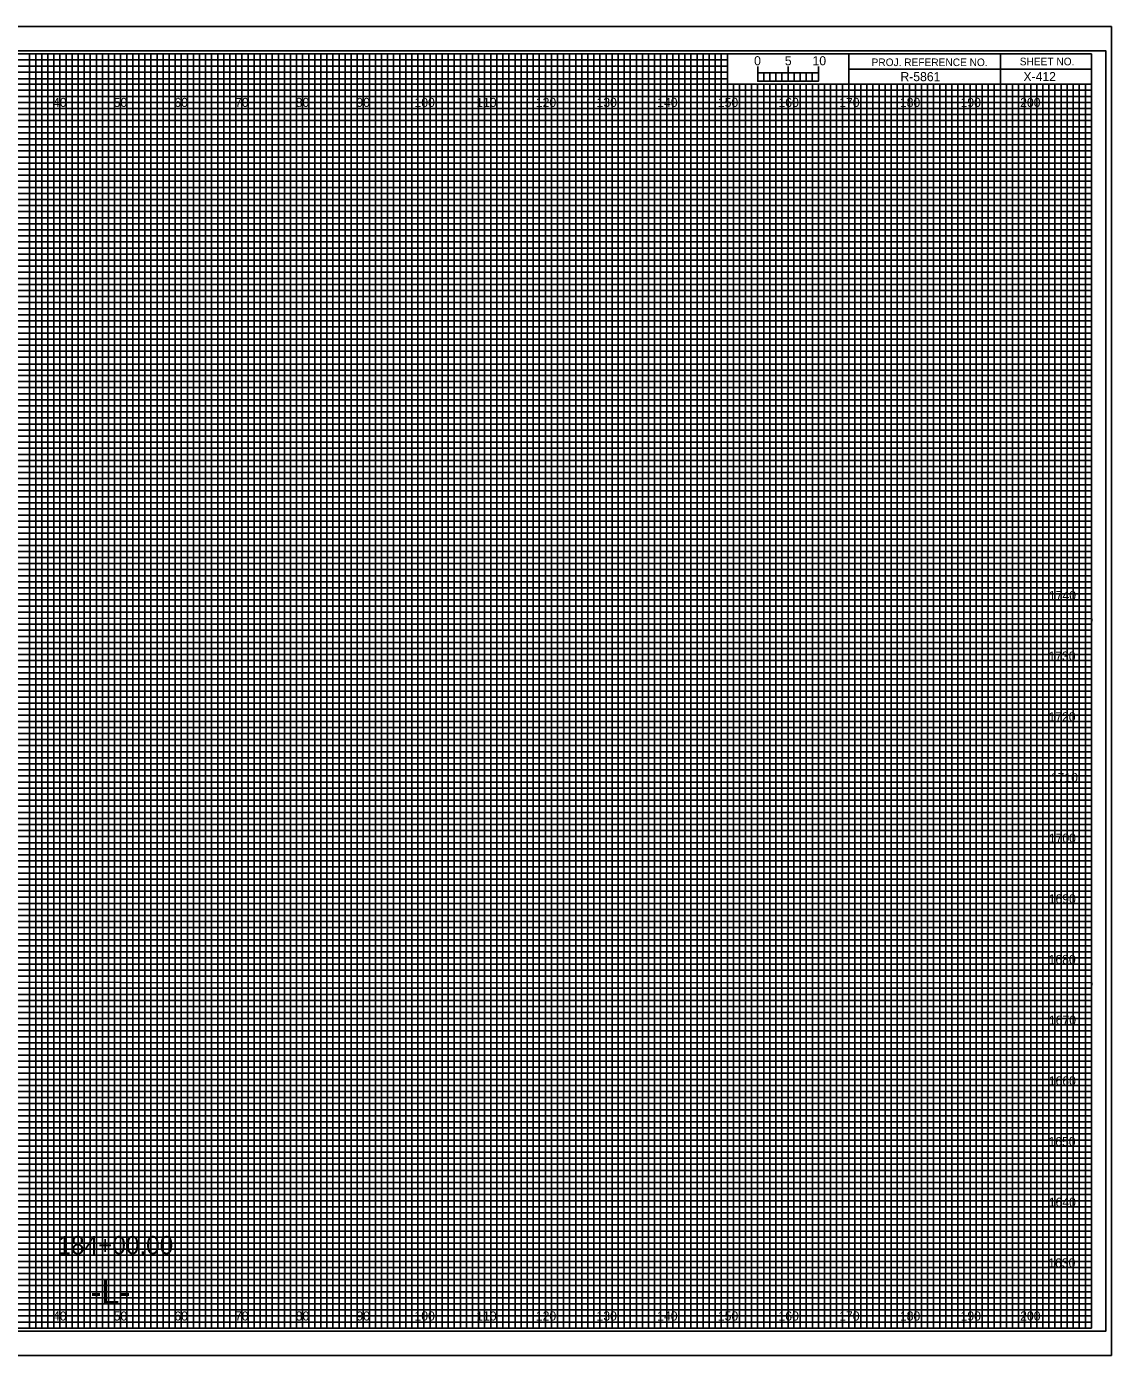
# Model space of a CAD drawing. Extents: x -13 to 323, y -5 to 6154.
# Drawn here: x 144.5 to 323.3, y 1755.5 to 1974.5 of the extents above; entities that cross this region are included whole.
import ezdxf

# ---------------------------------------------------------------- set-up
doc = ezdxf.new("R2010")
doc.units = 0
for name, color, linetype in [('Exist CMT Ground Line', 7, 'Continuous'), ('Prop Horizontal Alignment', 7, 'Continuous'), ('Prop Retaining Wall', 7, 'Continuous'), ('Prop XS Alignment Label', 7, 'Continuous'), ('Prop XS Bar Scale Labels', 7, 'Continuous'), ('Prop XS DDE', 7, 'Continuous'), ('Prop XS DDE Elevations', 7, 'Continuous'), ('Prop XS DDE Slope Text', 7, 'Continuous'), ('Prop XS Earthwork Shape', 7, 'Continuous'), ('Prop XS Elevation Labels', 7, 'Continuous'), ('Prop XS Project Number', 7, 'Continuous'), ('Prop XS Sheet Number', 7, 'Continuous'), ('Prop XS Station Labels', 7, 'Continuous'), ('Raster_Level_0', 7, 'Continuous'), ('Scratch_Level_3', 7, 'Continuous'), ('Sheet Cutting Line CELL', 7, 'Continuous')]:
    doc.layers.add(name, color=color, linetype=linetype)

msp = doc.modelspace()

# ---------------------------------------------------------------- linework, layer by layer
at = {"layer": 'Exist CMT Ground Line'}
for p, q in [((265, 1965.49), (265, 1967.9)), ((265, 1966.9), (265, 1967.9)), ((270, 1965.49), (270, 1967.9)), ((275, 1965.49), (275, 1967.9)), ((275, 1966.9), (275, 1967.9))]:
    msp.add_line(p, q, dxfattribs=at)
for points in [[(275, 1966.9), (265, 1966.9), (265, 1965.49), (275, 1965.49)], [(265, 1966.9), (266, 1966.9), (266, 1965.49), (265, 1965.49)], [(267, 1966.9), (268, 1966.9), (268, 1965.49), (267, 1965.49)], [(269, 1966.9), (270, 1966.9), (270, 1965.49), (269, 1965.49)], [(271, 1966.9), (272, 1966.9), (272, 1965.49), (271, 1965.49)], [(273, 1966.9), (274, 1966.9), (274, 1965.49), (273, 1965.49)]]:
    msp.add_lwpolyline(points, close=True, dxfattribs=at)
at = {"layer": 'Prop Retaining Wall'}
for p, q in [((0, 1969), (260, 1969)), ((260, 1969), (260, 1967.98)), ((260, 1967.98), (0, 1967.98)), ((0, 1967), (260, 1967)), ((260, 1967), (260, 1965.89)), ((260, 1965.89), (0, 1965.89)), ((0, 1964), (320, 1964))]:
    msp.add_line(p, q, dxfattribs=at)
for points in [[(0, 1963), (270, 1963), (320, 1963), (320, 1962), (0, 1962)], [(0, 1961), (320, 1961), (320, 1959), (0, 1959)], [(0, 1958), (320, 1958), (320, 1957), (0, 1956.98)], [(0, 1956), (320, 1956), (320, 1954), (0, 1954)], [(0, 1953), (320, 1953), (320, 1952), (0, 1952)], [(0, 1951), (320, 1951), (320, 1949), (0, 1949)], [(0, 1948), (320, 1948), (320, 1947), (0, 1947)], [(0, 1946), (320, 1946), (320, 1944), (0, 1944)], [(0, 1943), (320, 1943), (320, 1942), (0, 1942)], [(0, 1941), (320, 1941), (320, 1939), (0, 1939)], [(0, 1938), (320, 1938), (320, 1937), (0, 1937)], [(0, 1936), (320, 1936), (320, 1933.95), (320, 1933), (320, 1932), (0, 1932)], [(0, 1934), (320, 1934), (320, 1933), (0, 1933)], [(0, 1931), (320, 1931), (320, 1929), (0, 1929.03)], [(0, 1929.03), (320, 1929), (320, 1928), (0, 1928)], [(0, 1927), (320, 1927), (320, 1926), (0, 1926)], [(0, 1924), (320, 1924), (320, 1923), (0, 1923)], [(0, 1922), (320, 1922), (320, 1921), (0, 1921)], [(-0.07, 1918.89), (320, 1918.89), (320, 1917.88), (-0.07, 1917.88)], [(0, 1917), (320, 1917), (320, 1916), (0, 1916)], [(0, 1914), (320, 1914), (320, 1913), (0, 1913)], [(0, 1912), (320, 1912), (320, 1911), (0, 1911)], [(0, 1909), (320, 1909), (320, 1908), (0, 1908)], [(0, 1907), (320, 1907), (320, 1906), (0, 1906)], [(0, 1904), (320, 1904), (320, 1903), (0, 1903)], [(0, 1902), (320, 1902), (320, 1901), (0, 1901)], [(0, 1899), (320, 1899), (319.99, 1897.98), (0, 1898)], [(0, 1897), (320, 1897), (320, 1896), (0, 1896)], [(0, 1894), (320, 1894), (320, 1893), (0, 1893)], [(0, 1892), (320, 1892), (320, 1891), (0, 1891)], [(0, 1889), (320, 1889), (320, 1888), (0, 1888)], [(0, 1887), (320, 1887), (320, 1886), (0, 1886)], [(0, 1884), (320, 1884), (320, 1883), (0, 1883)], [(0, 1882), (320, 1882), (320, 1881), (0, 1881)], [(0, 1879), (320, 1879), (320, 1878), (0, 1878)], [(0, 1876.99), (320.07, 1876.91), (320, 1876), (0, 1876)], [(0, 1874), (320, 1874), (320, 1873), (0, 1873)], [(0, 1872), (320, 1872), (320, 1871), (0, 1871)], [(0, 1869), (320, 1869), (320, 1868), (0, 1868)], [(0, 1867), (320, 1867), (320, 1866), (0, 1866)], [(0, 1864), (320, 1864), (320, 1863), (0, 1863)], [(0, 1862), (320, 1862), (320, 1861), (0, 1861)], [(0, 1859), (320, 1859), (320, 1858), (0, 1858)], [(0, 1857), (320, 1857), (320, 1856), (0, 1856)], [(0, 1854), (320, 1854), (320, 1853), (0, 1853)], [(0, 1852), (320, 1852), (320, 1851), (0, 1851)], [(0, 1849), (320, 1849), (320, 1848), (0, 1848)], [(0, 1847), (320, 1847), (320, 1846), (0, 1846)], [(0, 1844), (320, 1844), (320, 1843), (0, 1843)], [(0, 1842), (320, 1842), (320, 1841), (0, 1841)], [(0, 1839), (320, 1839), (319.99, 1837.98), (0, 1838)], [(0, 1837), (320, 1837), (320, 1836), (0, 1836)], [(0, 1834), (320, 1834), (320, 1833), (0, 1833)], [(0, 1832), (320, 1832), (320, 1831), (0, 1831)], [(0, 1829), (320, 1829), (320, 1828), (0, 1828)], [(0, 1827), (320, 1827), (320, 1826), (0, 1826)], [(0, 1824), (320, 1824), (320, 1823), (0, 1823)], [(0, 1822), (320, 1822), (320, 1821), (0, 1821)], [(0, 1819), (320, 1819), (320, 1818), (0, 1818)], [(0, 1816.99), (320.07, 1816.91), (320, 1816), (0, 1816)], [(0, 1814), (320, 1814), (320, 1813), (0, 1813)], [(0, 1812), (320, 1812), (320, 1811), (0, 1811)], [(0, 1809), (320, 1809), (320, 1808), (0, 1808)], [(0, 1807), (320, 1807), (320, 1806), (0, 1806)], [(0, 1804), (320, 1804), (320, 1803), (0, 1803)], [(0, 1802), (320, 1802), (320, 1801), (0, 1801)], [(0, 1799), (320, 1799), (320, 1798), (0, 1798)], [(0, 1797), (320, 1797), (320, 1796), (0, 1796)], [(0, 1794), (320, 1794), (320, 1793), (0, 1793)], [(0, 1792), (320, 1792), (320, 1791), (0, 1791)], [(0, 1789), (320, 1789), (320, 1788), (0, 1788)], [(0, 1787), (320, 1787), (320, 1786), (0, 1786)], [(0, 1784), (320, 1784), (320, 1783), (0, 1783)], [(0, 1782), (320, 1782), (320, 1781), (0, 1781)], [(0, 1779), (320, 1779), (320, 1778), (0, 1778)], [(0, 1777), (320, 1777), (320, 1776), (0, 1776)], [(0, 1774), (320, 1774), (320, 1773), (0, 1773)], [(0, 1772), (320, 1772), (320, 1771), (0, 1771)], [(0, 1769), (320, 1769), (320, 1768), (0, 1768)], [(0, 1767), (320, 1767), (320, 1766), (0, 1766)], [(0, 1764), (320, 1764), (320, 1763), (0, 1763)], [(0, 1762), (320, 1762), (320, 1761), (0, 1761)]]:
    msp.add_lwpolyline(points, dxfattribs=at)
at = {"layer": 'Prop XS Alignment Label'}
for p, q in [((305, 1970), (305, 1965)), ((305, 1965), (305, 1970)), ((280, 1967.5), (280, 1965)), ((320, 1967.49), (280, 1967.49)), ((280, 1965), (320, 1965))]:
    msp.add_line(p, q, dxfattribs=at)
for points in [[(320, 1970), (0, 1970), (0, 1760), (320, 1760)], [(280, 1970), (260, 1970), (260, 1965.03), (280, 1965.03)], [(320, 1970), (280, 1970), (280, 1965), (320, 1965)]]:
    msp.add_lwpolyline(points, close=True, dxfattribs=at)
at = {"layer": 'Prop XS DDE'}
msp.add_lwpolyline([(-13.4, 1755.5), (323.3, 1755.5), (323.3, 1974.5), (-13.4, 1974.5)], close=True, dxfattribs=at)
at = {"layer": 'Prop XS DDE Elevations'}
for p, q in [((150, 1760), (150, 1970)), ((160, 1760), (160, 1970)), ((170, 1760), (170, 1970)), ((180, 1760), (180, 1970)), ((190, 1760), (190, 1970)), ((200, 1760), (200, 1970)), ((210, 1760), (210, 1970)), ((220, 1760), (220, 1970)), ((230, 1760), (230, 1970)), ((240, 1760), (240, 1970)), ((250, 1760), (250, 1970)), ((260, 1760), (260, 1964.69)), ((270, 1760), (270, 1964.69)), ((280, 1760), (280, 1964.69)), ((290, 1760), (290, 1964.69)), ((300, 1760), (300, 1964.69)), ((310, 1760), (310, 1964.69)), ((0, 1960), (320, 1960)), ((0, 1950), (320, 1950)), ((0, 1940), (320, 1940)), ((0, 1930), (320, 1930)), ((0, 1920), (320, 1920)), ((0, 1910), (320, 1910)), ((0, 1900), (320, 1900)), ((0, 1890), (320, 1890)), ((0, 1880), (320, 1880)), ((0, 1870), (320, 1870)), ((0, 1860), (320, 1860)), ((0, 1850), (320, 1850)), ((0, 1840), (320, 1840)), ((0, 1830), (320, 1830)), ((0, 1820), (320, 1820)), ((0, 1810), (320, 1810)), ((0, 1800), (320, 1800)), ((0, 1790), (320, 1790)), ((0, 1780), (320, 1780)), ((0, 1770), (320, 1770))]:
    msp.add_line(p, q, dxfattribs=at)
at = {"layer": 'Prop XS DDE Slope Text'}
msp.add_lwpolyline([(-10.8, 1759.5), (322.4, 1759.5), (322.4, 1970.5), (-10.8, 1970.5)], close=True, dxfattribs=at)
at = {"layer": 'Prop XS Earthwork Shape'}
for p, q in [((150, 1970), (140, 1970)), ((150, 1760), (150, 1970)), ((170, 1970), (160, 1970)), ((160, 1970), (160, 1760)), ((170, 1760), (170, 1970)), ((190, 1970), (180, 1970)), ((180, 1970), (180, 1760)), ((190, 1760), (190, 1970)), ((210, 1970), (200, 1970)), ((200, 1970), (200, 1760)), ((210, 1760), (210, 1970)), ((230, 1970), (220, 1970)), ((220, 1970), (220, 1760)), ((230, 1760), (230, 1970)), ((250, 1970), (240, 1970)), ((240, 1970), (240, 1760)), ((250, 1760), (250, 1970)), ((260, 1970), (260, 1760)), ((270, 1760), (270, 1965)), ((290, 1965), (280, 1965)), ((280, 1965), (280, 1760)), ((290, 1760), (290, 1965)), ((310, 1965), (300, 1965)), ((300, 1965), (300, 1760)), ((310, 1760), (310, 1965)), ((160, 1760), (150, 1760)), ((180, 1760), (170, 1760)), ((200, 1760), (190, 1760)), ((220, 1760), (210, 1760)), ((240, 1760), (230, 1760)), ((260, 1760), (250, 1760)), ((280, 1760), (270, 1760)), ((300, 1760), (290, 1760)), ((320, 1760), (310, 1760)), ((320, 1760), (320, 1760))]:
    msp.add_line(p, q, dxfattribs=at)
for points in [[(0, 1960), (320, 1960), (320, 1950), (0, 1950)], [(0, 1940), (320, 1940), (320, 1930), (0, 1930)], [(0, 1920), (320, 1920), (320, 1910), (0, 1910)], [(0, 1900), (320, 1900), (320, 1890), (0, 1890)], [(0, 1880), (320, 1880), (320, 1870), (0, 1870)], [(0, 1860), (320, 1860), (320, 1850), (0, 1850)], [(0, 1840), (320, 1840), (320, 1830), (0, 1830)], [(0, 1820), (320, 1820), (320, 1810), (0, 1810)], [(0, 1800), (320, 1800), (320, 1790), (0, 1790)], [(0, 1780), (320, 1780), (320, 1770), (0, 1770)]]:
    msp.add_lwpolyline(points, dxfattribs=at)
at = {"layer": 'Prop XS Elevation Labels'}
for p, q in [((267, 1965), (266.01, 1965)), ((266.01, 1965), (266.01, 1760)), ((267, 1760), (267, 1965)), ((269, 1965), (268, 1965)), ((268, 1965), (268, 1760)), ((269, 1760), (269, 1965)), ((266.01, 1760), (265, 1760)), ((268, 1760), (267, 1760))]:
    msp.add_line(p, q, dxfattribs=at)
for points in [[(145, 1760), (146, 1760), (146, 1970), (147, 1970), (147, 1760)], [(147, 1760), (148, 1760), (148, 1970), (149, 1970), (149, 1760)], [(150, 1760), (151, 1760), (151, 1970), (152, 1970), (152, 1760)], [(152, 1760), (153, 1760), (153, 1970), (154, 1970), (154, 1760)], [(155, 1760), (156, 1760), (156, 1970), (157, 1970), (157, 1760)], [(157, 1760), (158, 1760), (158, 1970), (159, 1970), (159, 1760)], [(160, 1760), (161, 1760), (161, 1970), (162, 1970), (162, 1760)], [(162, 1760), (163, 1760), (163, 1970), (164, 1970), (164, 1760)], [(165, 1760), (166, 1760), (166, 1970), (167, 1970), (167, 1760)], [(167, 1760), (168, 1760), (168, 1970), (169, 1970), (169, 1760)], [(170, 1760), (171, 1760), (171, 1970), (172, 1970), (172, 1760)], [(172, 1760), (173, 1760), (173, 1970), (174, 1970), (174, 1760)], [(175, 1760), (176, 1760), (176, 1970), (177, 1970), (177, 1760)], [(177, 1760), (178, 1760), (178, 1970), (179, 1970), (179, 1760)], [(180, 1760), (181, 1760), (181, 1970), (182, 1970), (182, 1760)], [(182, 1760), (183, 1760), (183, 1970), (184, 1970), (184, 1760)], [(185, 1760), (186, 1760), (186, 1970), (187, 1970), (187, 1760)], [(187, 1760), (188, 1760), (188, 1970), (189, 1970), (189, 1760)], [(190, 1760), (191, 1760), (191, 1970), (192, 1970), (192, 1760)], [(192, 1760), (193, 1760), (193, 1970), (194, 1970), (194, 1760)], [(195, 1760), (196, 1760), (196, 1970), (197, 1970), (197, 1760)], [(197, 1760), (198, 1760), (198, 1970), (199, 1970), (199, 1760)], [(200, 1760), (201, 1760), (201, 1970), (202, 1970), (202, 1760)], [(202, 1760), (203, 1760), (203, 1970), (204, 1970), (204, 1760)], [(205, 1760), (206, 1760), (206, 1970), (207, 1970), (207, 1760)], [(207, 1760), (208, 1760), (208, 1970), (209, 1970), (209, 1760)], [(210, 1760), (211, 1760), (211, 1970), (212, 1970), (212, 1760)], [(212, 1760), (213, 1760), (213, 1970), (214, 1970), (214, 1760)], [(215, 1760), (216, 1760), (216, 1970), (217, 1970), (217, 1760)], [(217, 1760), (218, 1760), (218, 1970), (219, 1970), (219, 1760)], [(220, 1760), (221, 1760), (221, 1970), (222, 1970), (222, 1760)], [(222, 1760), (223, 1760), (223, 1970), (224, 1970), (224, 1760)], [(225, 1760), (226, 1760), (226, 1970), (227, 1970), (227, 1760)], [(227, 1760), (228, 1760), (228, 1970), (229, 1970), (229, 1760)], [(230, 1760), (231, 1760), (231, 1970), (232, 1970), (232, 1760)], [(232, 1760), (233, 1760), (233, 1970), (234, 1970), (234, 1760)], [(235, 1760), (236, 1760), (236, 1970), (237, 1970), (237, 1760)], [(237, 1760), (238, 1760), (238, 1970), (239, 1970), (239, 1760)], [(240, 1760), (241, 1760), (241, 1970), (242, 1970), (242, 1760)], [(242, 1760), (243, 1760), (243, 1970), (244, 1970), (244, 1760)], [(245, 1760), (246, 1760), (246, 1970), (247, 1970), (247, 1760)], [(247, 1760), (248, 1760), (248, 1970), (249, 1970), (249, 1760)], [(250, 1760), (251, 1760), (251, 1970), (252, 1970), (252, 1760)], [(252, 1760), (253, 1760), (253, 1970), (254, 1970), (254, 1760)], [(255, 1760), (256, 1760), (256, 1970), (257, 1970), (257, 1760)], [(257, 1760), (258, 1760), (258, 1970), (259, 1970), (259, 1760)], [(260, 1760), (261, 1760), (261, 1965), (262.02, 1965), (262.02, 1760)], [(262, 1760), (263, 1760), (263, 1965), (263.99, 1965), (263.99, 1760)], [(270, 1760), (270.98, 1760), (270.98, 1965), (272, 1965), (272, 1760)], [(272, 1760), (273, 1760), (273, 1965), (274.05, 1965), (274.05, 1760)], [(275, 1760), (276, 1760), (276, 1965), (277, 1965), (277, 1760)], [(277, 1760), (278, 1760), (278, 1965), (279, 1965), (279, 1760)], [(280, 1760), (281, 1760), (281, 1965), (282, 1965), (282, 1760)], [(282, 1760), (283, 1760), (283, 1965), (284, 1965), (284, 1760)], [(285, 1760), (286, 1760), (286, 1965), (287, 1965), (287, 1760)], [(287, 1760), (288, 1760), (288, 1965), (289, 1965), (289, 1760)], [(290, 1760), (291, 1760), (291, 1965), (292, 1965), (292, 1760)], [(292, 1760), (293, 1760), (293, 1965), (294, 1965), (294, 1760)], [(295, 1760), (296, 1760), (296, 1965), (297, 1965), (297, 1760)], [(297, 1760), (298, 1760), (298, 1965), (299, 1965), (299, 1760)], [(300, 1760), (301, 1760), (301, 1965), (302, 1965), (302, 1760)], [(302, 1760), (303, 1760), (303, 1965), (304, 1965), (304, 1760)], [(305, 1760), (306, 1760), (306, 1965), (307, 1965), (307, 1760)], [(307, 1760), (308, 1760), (308, 1965), (309, 1965), (309, 1760)], [(310, 1760), (311, 1760), (311, 1965), (312, 1965), (312, 1760)], [(312, 1760), (313, 1760), (313, 1965), (314, 1965), (314, 1760)], [(315, 1760), (316, 1760), (316, 1965), (317, 1965), (317, 1760)], [(317, 1760), (318, 1760), (318, 1965), (319, 1965), (319, 1760)]]:
    msp.add_lwpolyline(points, dxfattribs=at)
at = {"layer": 'Prop XS Station Labels'}
for points in [[(135, 1970), (145, 1970), (145, 1760), (155, 1760), (155, 1970), (165, 1970), (165, 1760), (175, 1760), (175, 1970), (185, 1970), (185, 1760), (195, 1760), (195, 1970), (205, 1970), (205, 1760), (215, 1760), (215, 1970), (225, 1970), (225, 1760), (235, 1760), (235, 1970), (245, 1970), (245, 1760), (255, 1760), (255, 1970), (259.93, 1970), (260, 1970), (260, 1965), (264.99, 1965), (264.99, 1760), (275, 1760), (275, 1965), (285, 1965), (285, 1760), (295, 1760), (295, 1965), (305, 1965), (305, 1760), (315, 1760), (315, 1965)], [(0, 1965), (275, 1965)], [(0, 1945), (320, 1945), (320, 1955), (0, 1955)], [(0, 1925), (320, 1925), (320, 1935), (0, 1935)], [(0, 1905), (320, 1905), (320, 1915), (0, 1915)], [(0, 1885), (320, 1885), (320, 1895), (0, 1895)], [(0, 1865), (320, 1865), (320, 1875), (0, 1875)], [(0, 1845), (320, 1845), (320, 1855), (0, 1855)], [(0, 1825), (320, 1825), (320, 1835), (0, 1835)], [(0, 1805), (320, 1805), (320, 1815), (0, 1815)], [(0, 1785), (320, 1785), (320, 1795), (0, 1795)], [(0, 1765), (320, 1765), (320, 1775), (0, 1775)]]:
    msp.add_lwpolyline(points, dxfattribs=at)
at = {"layer": 'Sheet Cutting Line CELL'}
for p, q in [((323.3, 1974.5), (-13.4, 1974.5)), ((-13.4, 1755.5), (323.3, 1755.5))]:
    msp.add_line(p, q, dxfattribs=at)

# ---------------------------------------------------------------- texts
at = {"layer": 'Exist CMT Ground Line'}
msp.add_text('0', height=1.5, dxfattribs=at).set_placement((264.41, 1968.12))
at = {"layer": 'Prop Horizontal Alignment'}
msp.add_text('184+00.00', height=3, dxfattribs=at).set_placement((149.59, 1772.18))
at = {"layer": 'Prop XS Alignment Label'}
for s, height, p in [('PROJ. REFERENCE NO.', 1.25, (283.77, 1967.99)), ('SHEET NO.', 1.25, (308.19, 1968.12)), ('-L-', 4, (155.06, 1764))]:
    msp.add_text(s, height=height, dxfattribs=at).set_placement(p)
at = {"layer": 'Prop XS Bar Scale Labels'}
for s, p in [('5', (269.47, 1968.12)), ('10', (274.04, 1968.12))]:
    msp.add_text(s, height=1.5, dxfattribs=at).set_placement(p)
at = {"layer": 'Prop XS Project Number'}
msp.add_text('R-5861', height=1.5, dxfattribs=at).set_placement((288.53, 1965.5))
at = {"layer": 'Prop XS Sheet Number'}
msp.add_text('X-412', height=1.5, dxfattribs=at).set_placement((308.8, 1965.51))
at = {"layer": 'Raster_Level_0'}
for s, p in [('40', (148.86, 1961.25)), ('50', (158.86, 1961.25)), ('60', (168.86, 1961.25)), ('70', (178.86, 1961.25)), ('80', (188.86, 1961.25)), ('90', (198.86, 1961.25)), ('100', (208.44, 1961.25)), ('110', (218.62, 1961.25)), ('120', (228.44, 1961.25)), ('130', (238.44, 1961.25)), ('140', (248.44, 1961.25)), ('150', (258.44, 1961.25)), ('160', (268.44, 1961.25)), ('170', (278.44, 1961.25)), ('180', (288.44, 1961.25)), ('190', (298.44, 1961.25)), ('200', (308.26, 1961.25)), ('40', (148.86, 1761.25)), ('50', (158.86, 1761.25)), ('60', (168.86, 1761.25)), ('70', (178.86, 1761.25)), ('80', (188.86, 1761.25)), ('90', (198.86, 1761.25)), ('100', (208.44, 1761.25)), ('110', (218.62, 1761.25)), ('120', (228.44, 1761.25)), ('130', (238.44, 1761.25)), ('140', (248.44, 1761.25)), ('150', (258.44, 1761.25)), ('160', (268.44, 1761.25)), ('170', (278.44, 1761.25)), ('180', (288.44, 1761.25)), ('190', (298.44, 1761.25)), ('200', (308.26, 1761.25))]:
    msp.add_text(s, height=1.5, dxfattribs=at).set_placement(p)
at = {"layer": 'Scratch_Level_3'}
for s, p in [('1740', (313, 1880)), ('1730', (312.92, 1870)), ('1720', (312.93, 1860)), ('1710', (313.31, 1850)), ('1700', (312.98, 1840)), ('1690', (312.97, 1830)), ('1680', (312.95, 1820)), ('1670', (313, 1810)), ('1660', (312.97, 1800)), ('1650', (312.92, 1790)), ('1640', (312.97, 1780)), ('1630', (312.89, 1770))]:
    msp.add_text(s, height=1.5, dxfattribs=at).set_placement(p)

doc.saveas('drawing.dxf')
